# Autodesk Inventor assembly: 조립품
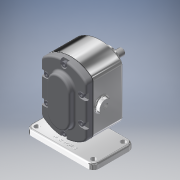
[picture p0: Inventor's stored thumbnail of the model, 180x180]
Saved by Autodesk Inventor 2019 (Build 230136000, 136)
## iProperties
Created: 2019-03
Part Number: 조립품
Material: 일반
Document SubType Name: Assembly
Designer: User
Author: User
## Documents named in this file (11)
- C:\Users\User\Desktop\490307V1016\조립품.iam
- C:\Users\User\Desktop\490307V1016\본체.ipt
- C:\Users\User\Desktop\490307V1016\메인축.ipt
- C:\Users\User\Desktop\490307V1016\오일 실 16 28 7.ipt
- C:\Users\User\Desktop\490307V1016\키 6 x 6 x 18.ipt
- C:\Users\User\Desktop\490307V1016\서브축.ipt
- C:\Users\User\Desktop\490307V1016\베어링부시.ipt
- C:\Users\User\Desktop\490307V1016\스퍼기어.ipt
- C:\Users\User\Desktop\490307V1016\개스킷.ipt
- C:\Users\User\Desktop\490307V1016\볼트 M5.ipt
- C:\Users\User\Desktop\490307V1016\커버.ipt
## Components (1 placed, 1 different names)
1. 개스킷:1
